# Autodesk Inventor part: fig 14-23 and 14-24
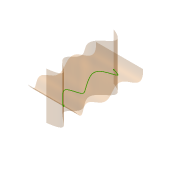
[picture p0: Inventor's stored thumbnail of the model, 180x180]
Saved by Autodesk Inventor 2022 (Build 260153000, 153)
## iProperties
Created: 2007-05
Part Number: fig 14-23 and 14-24
Document SubType Name: Modeling
Designer: Administrator
Density: 1 g/cm^3
Material: Generic
Appearance: Default
Author: Administrator
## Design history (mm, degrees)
node "Sketch1"
node "Sketch2"
sketch "Sketch3"
  geometry: 7 further points
  constraints: 7 other
extrude_surface "ExtrusionSrf1" sketch "Sketch3" dims "d0" = 50, "d1" = 0
sketch "Sketch4"
  geometry: 7 further points
  constraints: 7 other
extrude_surface "ExtrusionSrf2" sketch "Sketch4" dims "d2" = 50, "d3" = 0
sketch "3D Sketch1"
  node "3D Intersection1"
body "Srf1"
body "Srf2"
